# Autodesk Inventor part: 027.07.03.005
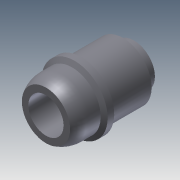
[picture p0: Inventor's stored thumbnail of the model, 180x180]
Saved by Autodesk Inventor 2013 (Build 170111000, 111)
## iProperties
Shininess: 25.0
Length Units: 11269
Angle Units: 11279
Time Units: 11290
Mass Units: 11283
Length Display Precision: 3
Angle Display Precision: 2
Created: 2002-01
Part Number: 027.07.03.005
Document SubType Name: Modeling
Designer: SaAlex
Material: Steel, Mild
Density: 7.86 g/cm^3
Density: 0.0
Volumn: 0.0
Area: 0.0
PropertySet Name: Model Information
Control State: 0
Master: False
Checked Out: False
Checked Out Date: 2008-10-15
Last Check In Date: 2008-10-15
Author: SaAlex
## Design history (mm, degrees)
feature "Base1"
body "Solid1"
